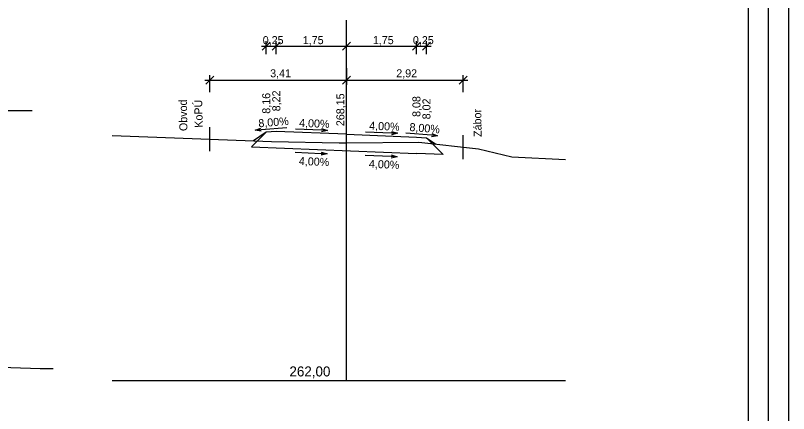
# Model space of a CAD drawing. Extents: x -763510.2 to -763467.2, y -1048902.9 to -1048872.2.
# Drawn here: x -763486.51 to -763467.21, y -1048892.94 to -1048883 of the extents above; entities that cross this region are included whole.
import ezdxf

# ---------------------------------------------------------------- set-up
doc = ezdxf.new("R2010")
doc.units = 0
for name, color, linetype in [('C3D-KORIDOR-SPOJNICE', 7, 'Continuous'), ('C3D-POPIS', 7, 'Continuous'), ('C3D-PR-POPIS-TEREN', 7, 'Continuous'), ('C3D-PR-TEREN', 7, 'Continuous'), ('C3D-ZOBPR-OSY', 7, 'Continuous'), ('C3D-ZOBPR-OSY-NADPIS', 7, 'Continuous'), ('Default', 7, 'Continuous'), ('U_formát', 7, 'Continuous'), ('U_rozvržení_rámeček', 7, 'Continuous'), ('Z_Pomocná', 7, 'Continuous')]:
    doc.layers.add(name, color=color, linetype=linetype)

# ---------------------------------------------------------------- blocks, each defined once
blk = doc.blocks.new('_Oblique')
at = {"layer": 'Default'}
blk.add_line((-0.5, -0.5), (0.5, 0.5), dxfattribs=at)
blk = doc.blocks.new('_Open30')
at = {"layer": 'Default'}
for p, q in [((-1, 0.27), (0, 0)), ((0, 0), (-1, -0.27)), ((0, 0), (-1, 0))]:
    blk.add_line(p, q, dxfattribs=at)
blk = doc.blocks.new('U1096')
at = {"layer": 'Default'}
blk.add_lwpolyline([(0, -297), (0, 0), (-420, 0), (-420, -297)], close=True, dxfattribs=at)
at = {"layer": 'U_formát'}
for points in [[(-425, 5), (5, 5), (5, -302), (-425, -302)], [(-5, -292), (-5, -5), (-415, -5), (-415, -292)]]:
    blk.add_lwpolyline(points, close=True, dxfattribs=at)

msp = doc.modelspace()

# ---------------------------------------------------------------- linework, layer by layer
at = {"layer": 'C3D-KORIDOR-SPOJNICE'}
for p, q in [((-763480.252, -1048885.915), (-763480.618, -1048886.281)), ((-763480.252, -1048885.915), (-763480.572, -1048886.128)), ((-763480.002, -1048885.895), (-763480.252, -1048885.915)), ((-763478.252, -1048885.965), (-763480.002, -1048885.895)), ((-763478.252, -1048885.965), (-763476.502, -1048886.035)), ((-763476.502, -1048886.035), (-763476.252, -1048886.055)), ((-763476.252, -1048886.055), (-763475.836, -1048886.472)), ((-763476.252, -1048886.055), (-763476.018, -1048886.211)), ((-763480.618, -1048886.281), (-763476.502, -1048886.445)), ((-763475.836, -1048886.472), (-763476.502, -1048886.445))]:
    msp.add_line(p, q, dxfattribs=at)
at = {"layer": 'C3D-POPIS'}
for p, q in [((-763480.252, -1048883.963), (-763480.252, -1048883.643)), ((-763480.002, -1048883.963), (-763480.002, -1048883.643)), ((-763478.252, -1048883.963), (-763478.252, -1048883.643)), ((-763476.502, -1048883.963), (-763476.502, -1048883.643)), ((-763476.252, -1048883.963), (-763476.252, -1048883.643)), ((-763480.372, -1048883.763), (-763478.132, -1048883.763)), ((-763478.372, -1048883.763), (-763476.132, -1048883.763))]:
    msp.add_line(p, q, dxfattribs=at)
for points in [[(-763480.383, -1048885.85), (-763479.735, -1048885.799)], [(-763478.875, -1048885.865), (-763479.524, -1048885.839)], [(-763477.125, -1048885.935), (-763477.774, -1048885.909)], [(-763476.122, -1048885.99), (-763476.77, -1048885.939)], [(-763478.882, -1048886.45), (-763479.531, -1048886.424)], [(-763477.132, -1048886.52), (-763477.781, -1048886.494)]]:
    msp.add_lwpolyline(points, dxfattribs=at)
at = {"layer": 'C3D-PR-TEREN'}
for points in [[(-763484.097, -1048885.999), (-763482.982, -1048886.035), (-763480.12, -1048886.146), (-763478.433, -1048886.18), (-763478.252, -1048886.178), (-763476.44, -1048886.164), (-763474.952, -1048886.329), (-763474.117, -1048886.53), (-763472.779, -1048886.592)], [(-763496.887, -1048891.415), (-763495.367, -1048891.474), (-763494.381, -1048891.564), (-763493.619, -1048891.634), (-763493.016, -1048891.656), (-763491.042, -1048891.68), (-763490.216, -1048891.69), (-763488.9, -1048891.713), (-763488.84, -1048891.735), (-763488.575, -1048891.732), (-763488.102, -1048891.738), (-763487.13, -1048891.778), (-763485.901, -1048891.816), (-763485.569, -1048891.814)]]:
    msp.add_lwpolyline(points, dxfattribs=at)
at = {"layer": 'C3D-ZOBPR-OSY'}
for p, q in [((-763478.252, -1048892.113), (-763478.252, -1048883.113)), ((-763496.887, -1048885.374), (-763486.095, -1048885.374)), ((-763484.097, -1048892.113), (-763472.779, -1048892.113))]:
    msp.add_line(p, q, dxfattribs=at)
at = {"layer": 'Default'}
for p, q in [((-763478.252, -1048884.31), (-763478.252, -1048884.73)), ((-763478.252, -1048884.31), (-763478.252, -1048884.73)), ((-763481.662, -1048884.91), (-763481.662, -1048884.49)), ((-763475.336, -1048884.91), (-763475.336, -1048884.49)), ((-763481.782, -1048884.61), (-763478.132, -1048884.61)), ((-763478.372, -1048884.61), (-763475.216, -1048884.61))]:
    msp.add_line(p, q, dxfattribs=at)
at = {"layer": 'Z_Pomocná'}
for points in [[(-763481.662, -1048886.386), (-763481.662, -1048886.086), (-763481.662, -1048885.786)], [(-763475.336, -1048886.587), (-763475.336, -1048886.287), (-763475.336, -1048885.987)]]:
    msp.add_lwpolyline(points, dxfattribs=at)

# ---------------------------------------------------------------- block references
at = {"layer": 'C3D-POPIS'}
for name, p, xscale, yscale, rotation in [('_Oblique', (-763480.252, -1048883.763), 0.2, 0.20000000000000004, 180), ('_Oblique', (-763480.002, -1048883.763), 0.2, 0.20000000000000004, 180), ('_Oblique', (-763478.252, -1048883.763), 0.2, 0.20000000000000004, 180), ('_Open30', (-763480.532, -1048885.862), 0.14999999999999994, 0.14999999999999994, -175.4260787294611), ('_Open30', (-763478.725, -1048885.871), 0.15000000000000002, 0.15000000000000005, -2.290610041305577), ('_Open30', (-763476.975, -1048885.941), 0.15000000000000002, 0.15000000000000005, -2.290610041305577), ('_Open30', (-763475.973, -1048886.002), 0.14999999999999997, 0.15, -4.573921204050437), ('_Open30', (-763478.732, -1048886.456), 0.15000000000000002, 0.15000000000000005, -2.290610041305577), ('_Open30', (-763476.982, -1048886.526), 0.15000000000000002, 0.15000000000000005, -2.290610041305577)]:
    msp.add_blockref(name, p, dxfattribs=dict(at, xscale=xscale, yscale=yscale, rotation=rotation))
at = {"layer": 'C3D-POPIS', "xscale": 0.2, "yscale": 0.20000000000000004}
for p in [(-763478.252, -1048883.763), (-763476.502, -1048883.763), (-763476.252, -1048883.763)]:
    msp.add_blockref('_Oblique', p, dxfattribs=at)
at = {"layer": 'Default', "xscale": 0.2, "yscale": 0.20000000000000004, "rotation": 180}
for p in [(-763481.662, -1048884.61), (-763478.252, -1048884.61)]:
    msp.add_blockref('_Oblique', p, dxfattribs=at)
at = {"layer": 'Default', "xscale": 0.2, "yscale": 0.20000000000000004}
for p in [(-763478.252, -1048884.61), (-763475.336, -1048884.61)]:
    msp.add_blockref('_Oblique', p, dxfattribs=at)
at = {"layer": 'U_rozvržení_rámeček', "xscale": 0.1, "yscale": 0.10000000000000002}
msp.add_blockref('U1096', (-763467.711, -1048872.685), dxfattribs=at)

# ---------------------------------------------------------------- texts
at = {"layer": 'C3D-POPIS'}
for s, p in [('0,25', (-763480.34, -1048883.714)), ('1,75', (-763479.34, -1048883.714)), ('1,75', (-763477.59, -1048883.714)), ('0,25', (-763476.59, -1048883.714))]:
    msp.add_text(s, height=0.2, dxfattribs=at).set_placement(p)
for s, rotation, p in [('8,22', 90, (-763479.902, -1048885.392)), ('8,16', 90, (-763480.152, -1048885.452)), ('268,15', 90, (-763478.302, -1048885.762)), ('268,15', 90, (-763478.302, -1048885.762)), ('8,08', 90, (-763476.402, -1048885.532)), ('8,02', 90, (-763476.152, -1048885.592)), ('8,00%', 4.5837, (-763480.441, -1048885.792)), ('4,00%', 357.7082, (-763479.435, -1048885.779)), ('4,00%', 357.7082, (-763477.685, -1048885.849)), ('8,00%', 355.4163, (-763476.682, -1048885.882)), ('4,00%', 357.7094, (-763479.441, -1048886.731)), ('4,00%', 357.7094, (-763477.691, -1048886.801))]:
    msp.add_text(s, height=0.2, rotation=rotation, dxfattribs=at).set_placement(p)
at = {"layer": 'C3D-PR-POPIS-TEREN'}
for s, p in [('Obvod ', (-763482.22, -1048885.883)), ('KoPÚ', (-763481.838, -1048885.799)), ('Zábor', (-763474.872, -1048886.03))]:
    msp.add_text(s, height=0.2, rotation=91.1271, dxfattribs=at).set_placement(p)
at = {"layer": 'C3D-ZOBPR-OSY-NADPIS'}
msp.add_text('262,00', height=0.25, rotation=360, dxfattribs=at).set_placement((-763479.673, -1048892.014))
at = {"layer": 'Default'}
for s, p in [('3,41', (-763480.154, -1048884.542)), ('2,92', (-763477.006, -1048884.542))]:
    msp.add_text(s, height=0.2, dxfattribs=at).set_placement(p)

doc.saveas('drawing.dxf')
